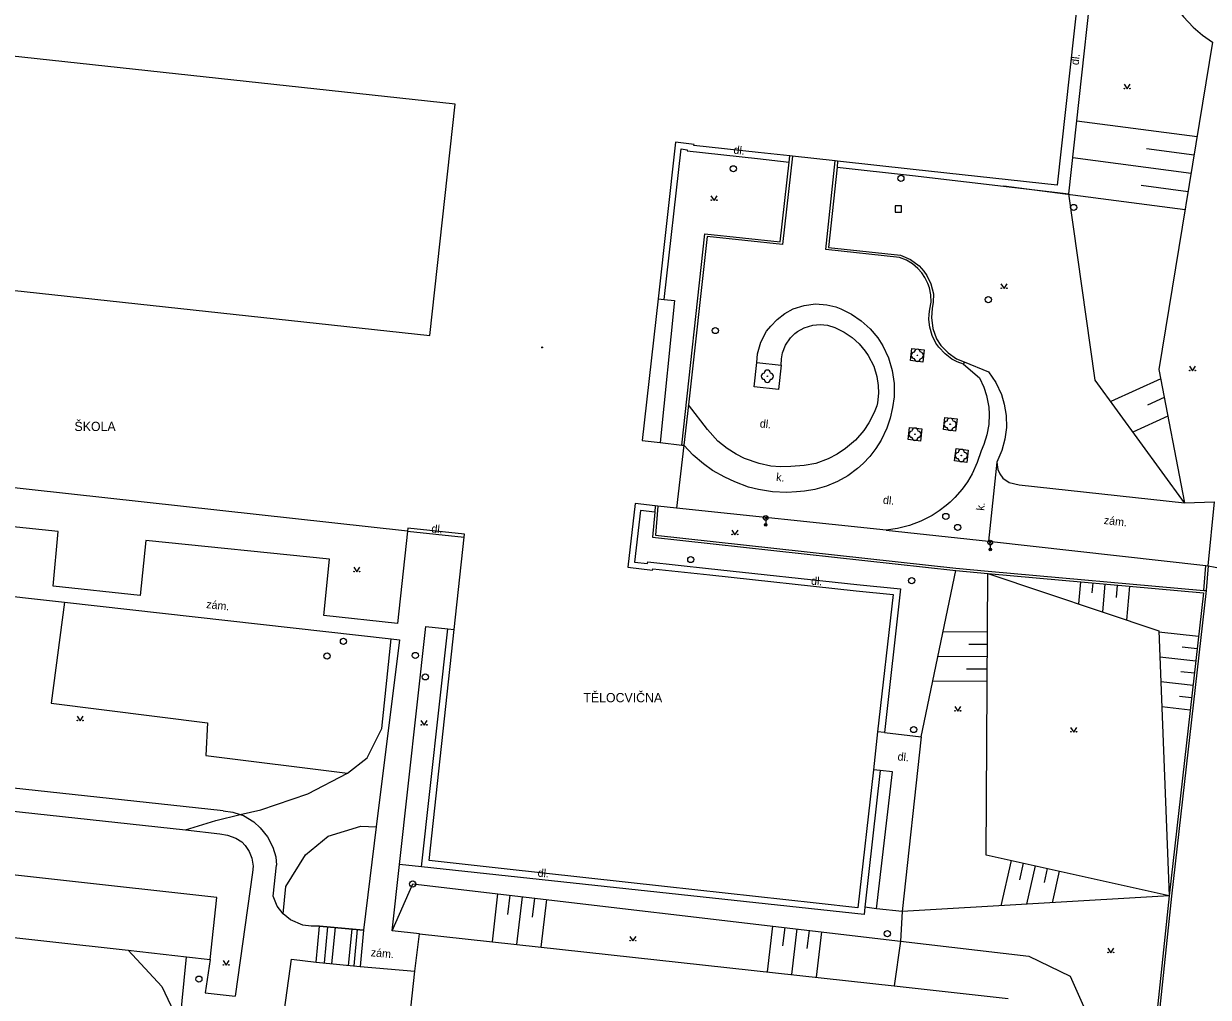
# Model space of a CAD drawing. Extents: x -602419 to -601554, y -1162937 to -1162362.
# Drawn here: x -602349.4 to -602253.1, y -1162646.7 to -1162567.6 of the extents above; entities that cross this region are included whole.
import ezdxf

# ---------------------------------------------------------------- set-up
doc = ezdxf.new("R2010")
doc.units = 0
doc.layers.add('Podklad', color=7, linetype='Continuous')

msp = doc.modelspace()

# ---------------------------------------------------------------- linework, layer by layer
at = {"layer": 'Podklad'}
for p, q in [((-602289.2325, -1162607.9), (-602288.9675, -1162607.635)), ((-602289.2325, -1162607.635), (-602288.9675, -1162607.9)), ((-602289.1, -1162607.955), (-602289.1, -1162608.33)), ((-602270.9925, -1162609.9), (-602270.7275, -1162609.635)), ((-602270.9925, -1162609.635), (-602270.7275, -1162609.9)), ((-602270.86, -1162609.955), (-602270.86, -1162610.33))]:
    msp.add_line(p, q, dxfattribs=at)
for points in [[(-602262.7199, -1162556.14), (-602265.43, -1162580.74)], [(-602264.4699, -1162581.45), (-602261.75, -1162556.46)], [(-602255.9, -1162566.18), (-602255.17, -1162567.08), (-602254.37, -1162567.9), (-602253.62, -1162568.55), (-602252.8, -1162569.12)], [(-602314.34, -1162574.17), (-602363.05, -1162568.87)], [(-602252.8, -1162569.12), (-602257.1599, -1162595.7199), (-602255.08, -1162606.53)], [(-602259.99, -1162572.545), (-602259.74, -1162572.92), (-602259.49, -1162572.545)], [(-602316.38, -1162592.96), (-602314.34, -1162574.17)], [(-602254.06, -1162576.82), (-602263.83, -1162575.55)], [(-602296.42, -1162577.26), (-602297.85, -1162589.96)], [(-602294.92, -1162577.43), (-602296.42, -1162577.26)], [(-602294.93, -1162577.51), (-602294.92, -1162577.43)], [(-602289.71, -1162578.08), (-602294.93, -1162577.51)], [(-602297.34, -1162590.02), (-602295.96, -1162577.8), (-602295.48, -1162577.86), (-602295.49, -1162577.95), (-602289.76, -1162578.58), (-602287.2, -1162578.86)], [(-602286.94, -1162578.38), (-602287.75, -1162585.57), (-602293.86, -1162584.92), (-602295.38, -1162598.57)], [(-602287.14, -1162578.36), (-602289.71, -1162578.08)], [(-602287.2, -1162578.86), (-602287.14, -1162578.36)], [(-602286.94, -1162578.38), (-602287.14, -1162578.36)], [(-602283.46, -1162578.76), (-602286.94, -1162578.38)], [(-602254.55, -1162579.79), (-602264.15, -1162578.53)], [(-602254.3, -1162578.3), (-602258.18, -1162577.8)], [(-602287.93, -1162585.35), (-602287.2, -1162578.86)], [(-602278.23, -1162586.62), (-602284.2199, -1162585.9699), (-602283.46, -1162578.76)], [(-602283.31, -1162579.28), (-602284, -1162585.8), (-602278.1599, -1162586.43)], [(-602283.26, -1162578.79), (-602283.46, -1162578.76)], [(-602283.26, -1162578.79), (-602283.31, -1162579.28)], [(-602283.31, -1162579.28), (-602277.18, -1162579.96), (-602264.4699, -1162581.45)], [(-602277.12, -1162579.46), (-602283.26, -1162578.79)], [(-602265.43, -1162580.74), (-602277.12, -1162579.46)], [(-602255.03, -1162582.75), (-602269.77, -1162580.83)], [(-602254.79, -1162581.27), (-602258.6, -1162580.77)], [(-602293.55, -1162581.605), (-602293.3, -1162581.98), (-602293.05, -1162581.605)], [(-602255.08, -1162606.53), (-602262.35, -1162596.57), (-602264.4699, -1162581.45)], [(-602295.9099, -1162601.85), (-602294.04, -1162584.7)], [(-602294.04, -1162584.7), (-602287.93, -1162585.35)], [(-602273.04, -1162595.28), (-602273.56, -1162595.1), (-602273.98, -1162594.87), (-602274.53, -1162594.45), (-602275.05, -1162593.89), (-602275.27, -1162593.57), (-602275.57, -1162592.94), (-602275.76, -1162592.27), (-602275.85, -1162591.6599), (-602275.82, -1162591.21), (-602275.76, -1162590.81), (-602275.67, -1162590.23), (-602275.69, -1162589.65), (-602275.8, -1162589.08), (-602275.93, -1162588.7199), (-602276.17, -1162588.23), (-602276.43, -1162587.85), (-602276.74, -1162587.51), (-602277.18, -1162587.14), (-602277.67, -1162586.83), (-602278.23, -1162586.62)], [(-602278.1599, -1162586.43), (-602277.35, -1162586.77), (-602276.63, -1162587.29), (-602276.25, -1162587.73), (-602276.01, -1162588.09), (-602275.68, -1162588.76), (-602275.48, -1162589.58), (-602275.49, -1162590.25), (-602275.57, -1162590.77), (-602275.63, -1162591.49), (-602275.52, -1162592.38), (-602275.2199, -1162593.21), (-602274.87, -1162593.77), (-602274.28, -1162594.37), (-602273.59, -1162594.85), (-602272.98, -1162595.09)], [(-602365.1, -1162587.6599), (-602316.38, -1162592.96)], [(-602269.99, -1162588.765), (-602269.74, -1162589.14), (-602269.49, -1162588.765)], [(-602297.85, -1162589.96), (-602299.15, -1162601.49)], [(-602297.85, -1162589.96), (-602297.34, -1162590.02)], [(-602297.34, -1162590.02), (-602296.5, -1162590.11)], [(-602296.5, -1162590.11), (-602297.67, -1162601.65)], [(-602289.82, -1162595.14), (-602289.76, -1162594.45), (-602289.49, -1162593.49), (-602289.03, -1162592.6), (-602288.69, -1162592.19), (-602288.18, -1162591.65), (-602287.55, -1162591.17), (-602286.86, -1162590.79), (-602285.98, -1162590.51), (-602285.06, -1162590.38), (-602284.14, -1162590.45), (-602283.4, -1162590.62), (-602283, -1162590.78), (-602282.14, -1162591.21), (-602281.34, -1162591.76), (-602280.63, -1162592.4099), (-602280, -1162593.15), (-602279.6, -1162593.79), (-602279.13, -1162594.76), (-602278.82, -1162595.79), (-602278.6599, -1162596.86), (-602278.6599, -1162597.94), (-602278.8, -1162598.8), (-602278.99, -1162599.6599), (-602279.27, -1162600.49), (-602279.73, -1162601.45), (-602280.15, -1162602.13), (-602280.64, -1162602.77), (-602281.19, -1162603.35), (-602281.65, -1162603.75), (-602282.43, -1162604.34), (-602283.27, -1162604.82), (-602284.17, -1162605.19), (-602285.11, -1162605.46), (-602285.96, -1162605.59), (-602286.59, -1162605.65), (-602287.39, -1162605.69), (-602288.55, -1162605.64), (-602289.69, -1162605.45), (-602290.49, -1162605.27), (-602291.62, -1162604.85), (-602292.43, -1162604.4699), (-602293.42, -1162603.9099), (-602294.1599, -1162603.38), (-602295.01, -1162602.6599), (-602295.75, -1162601.87)], [(-602287.84, -1162595.36), (-602287.83, -1162594.85), (-602287.73, -1162594.35), (-602287.5, -1162593.73), (-602287.08, -1162593.13), (-602286.73, -1162592.79), (-602286.52, -1162592.62), (-602285.99, -1162592.33), (-602285.27, -1162592.1), (-602284.68, -1162592.06), (-602284.08, -1162592.11), (-602283.5, -1162592.3), (-602282.7199, -1162592.67), (-602282.08, -1162593.11), (-602281.51, -1162593.63), (-602281.01, -1162594.2199), (-602280.77, -1162594.58), (-602280.33, -1162595.44), (-602280.07, -1162596.27), (-602279.96, -1162597.02), (-602279.94, -1162597.63), (-602280.02, -1162598.42), (-602280.08, -1162598.67), (-602280.29, -1162599.21), (-602280.7199, -1162600.05), (-602281.14, -1162600.67), (-602281.8, -1162601.45), (-602282.61, -1162602.13), (-602283.3, -1162602.59), (-602284.02, -1162602.9699), (-602285.02, -1162603.34), (-602285.9699, -1162603.51), (-602287.07, -1162603.6), (-602287.89, -1162603.61), (-602288.7, -1162603.56), (-602289.63, -1162603.36), (-602290.83, -1162602.94), (-602291.5, -1162602.6), (-602292.23, -1162602.14), (-602292.98, -1162601.52), (-602293.84, -1162600.58)], [(-602277.2199, -1162594), (-602276.23, -1162594.12), (-602276.35, -1162595.11), (-602277.34, -1162594.99), (-602277.2199, -1162594)], [(-602287.84, -1162595.36), (-602288.07, -1162597.35), (-602290.04, -1162597.12), (-602289.82, -1162595.14)], [(-602289.82, -1162595.14), (-602287.84, -1162595.36)], [(-602272.98, -1162595.09), (-602273.04, -1162595.28)], [(-602273.04, -1162595.28), (-602271.73, -1162596.38)], [(-602272.98, -1162595.09), (-602271.01, -1162595.89)], [(-602254.68, -1162595.445), (-602254.43, -1162595.82), (-602254.18, -1162595.445)], [(-602271.73, -1162596.38), (-602271.39, -1162597.14), (-602271.1599, -1162597.83), (-602270.9699, -1162598.76), (-602270.95, -1162599.34), (-602270.9699, -1162600.18), (-602271.13, -1162601.01), (-602271.37, -1162601.81), (-602271.61, -1162602.33), (-602271.93, -1162603.27), (-602272.34, -1162604.18), (-602272.71, -1162604.83), (-602273.15, -1162605.43), (-602273.73, -1162606.12), (-602274.11, -1162606.48), (-602274.44, -1162606.77), (-602275, -1162607.2), (-602275.59, -1162607.58), (-602276.49, -1162608.04), (-602277.43, -1162608.39), (-602278.4099, -1162608.64), (-602279.33, -1162608.75)], [(-602271.01, -1162595.89), (-602270.4, -1162596.77), (-602269.95, -1162597.74), (-602269.7199, -1162598.52), (-602269.57, -1162599.46), (-602269.55, -1162600.4099), (-602269.69, -1162601.36), (-602269.92, -1162602.28), (-602270.34, -1162603.23)], [(-602257.01, -1162596.48), (-602261.07, -1162598.32)], [(-602295.38, -1162598.57), (-602295.75, -1162601.87)], [(-602293.84, -1162600.58), (-602295.38, -1162598.57)], [(-602256.7199, -1162597.99), (-602258.1, -1162598.62)], [(-602274.55, -1162599.6), (-602273.56, -1162599.7199), (-602273.68, -1162600.71), (-602274.67, -1162600.59), (-602274.55, -1162599.6)], [(-602256.43, -1162599.5), (-602259.27, -1162600.79)], [(-602277.4099, -1162600.42), (-602276.42, -1162600.54), (-602276.54, -1162601.53), (-602277.53, -1162601.4099), (-602277.4099, -1162600.42)], [(-602299.15, -1162601.49), (-602297.67, -1162601.65)], [(-602297.67, -1162601.65), (-602295.9099, -1162601.85)], [(-602295.75, -1162601.87), (-602296.35, -1162606.98)], [(-602295.9099, -1162601.85), (-602295.75, -1162601.87)], [(-602273.64, -1162602.14), (-602272.65, -1162602.26), (-602272.77, -1162603.26), (-602273.77, -1162603.13), (-602273.64, -1162602.14)], [(-602318.2, -1162608.84), (-602319.03, -1162616.33), (-602325, -1162615.68), (-602324.53, -1162611.13), (-602339.45, -1162609.59), (-602339.9099, -1162614.08), (-602346.99, -1162613.31), (-602346.58, -1162608.86), (-602361.42, -1162607.34), (-602361.92, -1162611.68), (-602367.9099, -1162611.02), (-602367.1599, -1162603.46)], [(-602318.2, -1162608.84), (-602367.1599, -1162603.46)], [(-602270.34, -1162603.23), (-602271, -1162609.6599)], [(-602270.34, -1162603.23), (-602270.25, -1162603.84), (-602270.08, -1162604.2), (-602269.83, -1162604.55), (-602269.33, -1162604.89), (-602268.51, -1162605.07)], [(-602268.51, -1162605.07), (-602255.08, -1162606.53)], [(-602299.7199, -1162606.6), (-602300.31, -1162611.78)], [(-602298.12, -1162607.31), (-602299.27, -1162607.1599), (-602299.75, -1162611.35), (-602298.71, -1162611.46), (-602298.69, -1162611.34), (-602293.75, -1162611.87), (-602281.71, -1162613.18), (-602278.1599, -1162613.52), (-602279.46, -1162625.21)], [(-602298.08, -1162606.78), (-602299.7199, -1162606.6)], [(-602298.12, -1162607.31), (-602298.29, -1162609.34), (-602273.67, -1162612.05)], [(-602298.08, -1162606.78), (-602298.12, -1162607.31)], [(-602297.88, -1162606.81), (-602298.08, -1162606.78)], [(-602297.88, -1162606.81), (-602298.07, -1162609.1599), (-602273.65, -1162611.85), (-602271.03, -1162612.08), (-602253.52, -1162613.65)], [(-602296.35, -1162606.98), (-602297.88, -1162606.81)], [(-602279.33, -1162608.75), (-602296.35, -1162606.98)], [(-602255.08, -1162606.53), (-602252.64, -1162606.46)], [(-602253.1599, -1162611.65), (-602252.64, -1162606.46)], [(-602318.18, -1162608.59), (-602318.2, -1162608.84)], [(-602318.2, -1162608.84), (-602313.59, -1162609.34)], [(-602313.56, -1162609.1), (-602318.18, -1162608.59)], [(-602313.59, -1162609.34), (-602313.56, -1162609.1)], [(-602291.85, -1162608.755), (-602291.6, -1162609.13), (-602291.35, -1162608.755)], [(-602279.33, -1162608.75), (-602271, -1162609.6599)], [(-602314.4, -1162616.84), (-602313.59, -1162609.34)], [(-602271, -1162609.6599), (-602253.36, -1162611.63)], [(-602322.57, -1162611.775), (-602322.32, -1162612.15), (-602322.07, -1162611.775)], [(-602300.31, -1162611.78), (-602298.3, -1162612)], [(-602298.3, -1162612), (-602298.28, -1162611.89)], [(-602298.28, -1162611.89), (-602293.64, -1162612.39)], [(-602276.4699, -1162625.54), (-602273.67, -1162612.05)], [(-602273.67, -1162612.05), (-602271.05, -1162612.28)], [(-602253.52, -1162613.65), (-602253.36, -1162611.63)], [(-602253.36, -1162611.63), (-602253.1599, -1162611.65)], [(-602253.1599, -1162611.65), (-602253.31, -1162613.67)], [(-602253.1599, -1162611.65), (-602252.02, -1162611.88), (-602250.77, -1162612.48), (-602249.88, -1162613.05), (-602249.07, -1162613.87), (-602248.38, -1162614.79), (-602247.8, -1162616.04), (-602247.58, -1162617.08), (-602247.4699, -1162618.25)], [(-602333.18, -1162631.55), (-602369.52, -1162627.62), (-602367.45, -1162612.23), (-602346.07, -1162614.62), (-602319.53, -1162617.6), (-602318.86, -1162617.67), (-602320.74, -1162632.85), (-602321.78, -1162641.24)], [(-602293.64, -1162612.39), (-602281.76, -1162613.68)], [(-602256.33, -1162638.4699), (-602271.18, -1162635.15), (-602271.05, -1162612.28)], [(-602271.05, -1162612.28), (-602257.1599, -1162616.95), (-602256.33, -1162638.4699)], [(-602271.05, -1162612.28), (-602253.53, -1162613.85)], [(-602263.53, -1162612.95), (-602263.69, -1162614.75)], [(-602262.54, -1162613.04), (-602262.61, -1162613.86)], [(-602261.54, -1162613.13), (-602261.74, -1162615.4099)], [(-602406.42, -1162613.44), (-602407.63, -1162625.26), (-602370.74, -1162629.36), (-602336.25, -1162633.11), (-602333.45, -1162633.42)], [(-602253.31, -1162613.67), (-602256.13, -1162638.49), (-602260, -1162675.31), (-602321, -1162675.4699), (-602331.82, -1162673.96)], [(-602281.76, -1162613.68), (-602278.76, -1162614)], [(-602278.76, -1162614), (-602280.01, -1162625.15)], [(-602260.55, -1162613.2199), (-602260.64, -1162614.23)], [(-602259.55, -1162613.31), (-602259.8, -1162616.06)], [(-602253.53, -1162613.85), (-602256.33, -1162638.4699)], [(-602253.52, -1162613.65), (-602253.31, -1162613.67)], [(-602346.07, -1162614.62), (-602347.16, -1162622.82), (-602334.46, -1162624.41), (-602334.59, -1162627.06), (-602323.08, -1162628.51), (-602321.47, -1162627.25), (-602320.28, -1162624.87), (-602319.53, -1162617.6)], [(-602319.46, -1162641.31), (-602318.86, -1162635.92), (-602316.71, -1162616.59)], [(-602279.8, -1162628.29), (-602281.04, -1162639.39), (-602281.1, -1162639.97), (-602317.06, -1162636.11), (-602314.92, -1162616.79)], [(-602316.71, -1162616.59), (-602314.92, -1162616.79)], [(-602316.45, -1162635.6), (-602314.4, -1162616.84)], [(-602314.92, -1162616.79), (-602314.4, -1162616.84)], [(-602271.08, -1162617.05), (-602274.7, -1162617.03)], [(-602253.93, -1162617.4099), (-602257.1599, -1162617.05)], [(-602271.08, -1162618.05), (-602272.61, -1162618.04)], [(-602254.05, -1162618.4), (-602255.28, -1162618.27)], [(-602271.09, -1162619.05), (-602275.12, -1162619.03)], [(-602254.1599, -1162619.4), (-602257.08, -1162619.07)], [(-602271.09, -1162620.05), (-602272.79, -1162620.04)], [(-602254.27, -1162620.39), (-602255.38, -1162620.27)], [(-602271.1, -1162621.05), (-602275.53, -1162621.02)], [(-602254.39, -1162621.39), (-602257, -1162621.09)], [(-602254.5, -1162622.38), (-602255.48, -1162622.27)], [(-602273.75, -1162623.085), (-602273.5, -1162623.46), (-602273.25, -1162623.085)], [(-602254.61, -1162623.37), (-602256.92, -1162623.11)], [(-602345.05, -1162623.875), (-602344.8, -1162624.25), (-602344.55, -1162623.875)], [(-602317.11, -1162624.225), (-602316.86, -1162624.6), (-602316.61, -1162624.225)], [(-602280.01, -1162625.15), (-602280.35, -1162628.2199)], [(-602279.46, -1162625.21), (-602280.01, -1162625.15)], [(-602279.46, -1162625.21), (-602276.4699, -1162625.54)], [(-602276.4699, -1162625.54), (-602278.02, -1162639.74)], [(-602264.33, -1162624.7849), (-602264.08, -1162625.1599), (-602263.83, -1162624.7849)], [(-602336.25, -1162633.11), (-602333.77, -1162632.35), (-602331.8, -1162631.86), (-602330.13, -1162631.49), (-602326.3, -1162630.17), (-602323.08, -1162628.51)], [(-602280.35, -1162628.2199), (-602281.61, -1162639.44)], [(-602279.8, -1162628.29), (-602280.35, -1162628.2199)], [(-602278.02, -1162639.74), (-602280.1, -1162639.51), (-602278.8, -1162628.4), (-602279.8, -1162628.29)], [(-602334.24, -1162643.63), (-602333.7, -1162638.61), (-602399.43, -1162631.32), (-602413.2, -1162629.79), (-602413.76, -1162634.8), (-602399.17, -1162636.42), (-602340.91, -1162642.88), (-602336.16, -1162643.41)], [(-602333.18, -1162631.55), (-602332.4, -1162631.66), (-602331.8, -1162631.86), (-602331.53, -1162631.95), (-602330.68, -1162632.46), (-602330.17, -1162632.93), (-602329.57, -1162633.66), (-602329.14, -1162634.5), (-602328.91, -1162635.3), (-602328.85, -1162635.98)], [(-602328.31, -1162639.93), (-602328.08, -1162637.71), (-602326.5, -1162635.13), (-602324.64, -1162633.61), (-602322, -1162632.81), (-602320.74, -1162632.85)], [(-602333.45, -1162633.42), (-602332.82, -1162633.53), (-602332.15, -1162633.77), (-602331.67, -1162634.09), (-602331.39, -1162634.38), (-602331.06, -1162634.87), (-602330.84, -1162635.4099), (-602330.74, -1162636.05), (-602330.79, -1162636.58)], [(-602329.12, -1162638.49), (-602328.85, -1162635.98)], [(-602317.06, -1162636.11), (-602318.86, -1162635.92)], [(-602310.36, -1162636.27), (-602316.45, -1162635.6)], [(-602297.32, -1162637.71), (-602310.36, -1162636.27)], [(-602269.17, -1162635.6), (-602269.99, -1162639.27)], [(-602268.19, -1162635.82), (-602268.49, -1162637.17)], [(-602267.21, -1162636.04), (-602267.9099, -1162639.15)], [(-602266.24, -1162636.25), (-602266.49, -1162637.39)], [(-602340.91, -1162642.88), (-602338.17, -1162645.84), (-602336.71, -1162648.92), (-602335.81, -1162650.8), (-602334.91, -1162655.6), (-602335.55, -1162661.39), (-602338.33, -1162666.79), (-602341.98, -1162671), (-602347.06, -1162674.09), (-602351.26, -1162675.28), (-602355.87, -1162675.28), (-602392.78, -1162671.16), (-602397.78, -1162669.49), (-602400.24, -1162668.06), (-602403.1, -1162665.2), (-602405.72, -1162661.55), (-602407.46, -1162657.03), (-602408.02, -1162652.26), (-602407.38, -1162647.82), (-602405.56, -1162643.45), (-602402.94, -1162639.88), (-602400.24, -1162637.5), (-602399.17, -1162636.42)], [(-602330.79, -1162636.58), (-602332.21, -1162646.62)], [(-602265.26, -1162636.4699), (-602265.83, -1162639.03)], [(-602319.46, -1162641.31), (-602317.78, -1162637.5)], [(-602317.78, -1162637.5), (-602278.15, -1162642.14), (-602267.72, -1162643.36), (-602264.36, -1162645), (-602263.28, -1162647.42), (-602266.06, -1162675.13)], [(-602285.01, -1162639.06), (-602297.32, -1162637.71)], [(-602325.35, -1162640.93), (-602326.04, -1162640.93), (-602326.7199, -1162640.84), (-602327.7, -1162640.42), (-602328.31, -1162639.93), (-602328.78, -1162639.3), (-602329.12, -1162638.49)], [(-602310.88, -1162638.31), (-602311.33, -1162642.19)], [(-602309.89, -1162638.42), (-602310.07, -1162639.9699)], [(-602308.89, -1162638.54), (-602309.34, -1162642.4099)], [(-602307.9, -1162638.6599), (-602308.08, -1162640.2)], [(-602306.9099, -1162638.77), (-602307.36, -1162642.62)], [(-602281.61, -1162639.44), (-602285.01, -1162639.06)], [(-602256.33, -1162638.4699), (-602278.02, -1162639.74)], [(-602256.33, -1162638.4699), (-602260.18, -1162675.11), (-602266.06, -1162675.13)], [(-602280.1, -1162639.51), (-602281.04, -1162639.39)], [(-602278.02, -1162639.74), (-602278.15, -1162642.14), (-602278.67, -1162645.77)], [(-602325.63, -1162643.85), (-602325.35, -1162640.93)], [(-602325.35, -1162640.93), (-602321.78, -1162641.24)], [(-602321.78, -1162641.24), (-602325.35, -1162640.93)], [(-602324.7, -1162640.99), (-602324.98, -1162643.9099)], [(-602324.34, -1162643.98), (-602324.06, -1162641.04)], [(-602288.55, -1162640.92), (-602288.99, -1162644.64)], [(-602287.56, -1162641.04), (-602287.73, -1162642.52)], [(-602322.74, -1162641.1599), (-602323.03, -1162644.11)], [(-602322.54, -1162644.15), (-602322.26, -1162641.2)], [(-602321.78, -1162641.24), (-602322.06, -1162644.2)], [(-602317.24, -1162641.54), (-602319.46, -1162641.31)], [(-602317.62, -1162644.58), (-602317.24, -1162641.54)], [(-602317.24, -1162641.54), (-602278.67, -1162645.77), (-602269.4, -1162646.79)], [(-602300.14, -1162641.755), (-602299.89, -1162642.13), (-602299.64, -1162641.755)], [(-602286.57, -1162641.15), (-602287, -1162644.86)], [(-602285.57, -1162641.27), (-602285.75, -1162642.75)], [(-602284.58, -1162641.39), (-602285.01, -1162645.08)], [(-602261.31, -1162642.705), (-602261.06, -1162643.08), (-602260.81, -1162642.705)], [(-602332.81, -1162651.12), (-602335.81, -1162650.8), (-602336.88, -1162650.68), (-602336.71, -1162648.92), (-602336.16, -1162643.41)], [(-602336.1599, -1162643.4099), (-602334.24, -1162643.63)], [(-602334.24, -1162643.63), (-602334.64, -1162646.35), (-602332.21, -1162646.62)], [(-602333.19, -1162643.725), (-602332.94, -1162644.1), (-602332.69, -1162643.725)], [(-602331.79, -1162673.76), (-602327.62, -1162643.61)], [(-602327.62, -1162643.61), (-602325.63, -1162643.85)], [(-602325.63, -1162643.85), (-602322.06, -1162644.2)], [(-602325.63, -1162643.85), (-602322.06, -1162644.2)], [(-602322.06, -1162644.2), (-602317.62, -1162644.58)], [(-602320.1, -1162667.64), (-602317.62, -1162644.58)]]:
    msp.add_lwpolyline(points, dxfattribs=at)
msp.add_lwpolyline([(-602278.58, -1162582.93), (-602278.08, -1162582.93), (-602278.08, -1162582.43), (-602278.58, -1162582.43)], close=True, dxfattribs=at)
for centre, radius in [((-602259.9651, -1162572.8949), 0.025), ((-602259.5154, -1162572.8949), 0.025), ((-602291.73, -1162579.4099), 0.25), ((-602278.12, -1162580.18), 0.25), ((-602293.5251, -1162581.9549), 0.025), ((-602293.0754, -1162581.9549), 0.025), ((-602264.08, -1162582.55), 0.25), ((-602269.9651, -1162589.1149), 0.025), ((-602269.5154, -1162589.1149), 0.025), ((-602271.02, -1162590.04), 0.25), ((-602293.2, -1162592.55), 0.25), ((-602307.27, -1162593.92), 0.045), ((-602307.27, -1162593.92), 0.0199), ((-602276.78, -1162594.56), 0.025), ((-602254.6551, -1162595.7949), 0.025), ((-602254.2054, -1162595.7949), 0.025), ((-602288.9699, -1162596.26), 0.025), ((-602274.12, -1162600.1599), 0.025), ((-602276.98, -1162600.9699), 0.025), ((-602273.21, -1162602.7), 0.025), ((-602274.4699, -1162607.65), 0.25), ((-602289.1, -1162607.7675), 0.1875), ((-602289.1, -1162608.33), 0.1), ((-602289.1, -1162608.33), 0.0723), ((-602289.1, -1162608.33), 0.0438), ((-602273.51, -1162608.54), 0.25), ((-602291.8251, -1162609.1049), 0.025), ((-602291.3754, -1162609.1049), 0.025), ((-602270.86, -1162609.7675), 0.1875), ((-602270.86, -1162610.33), 0.1), ((-602270.86, -1162610.33), 0.0723), ((-602270.86, -1162610.33), 0.0438), ((-602295.19, -1162611.15), 0.25), ((-602322.5451, -1162612.1249), 0.025), ((-602322.0954, -1162612.1249), 0.025), ((-602277.24, -1162612.86), 0.25), ((-602323.4099, -1162617.79), 0.25), ((-602324.74, -1162618.98), 0.25), ((-602317.57, -1162618.94), 0.25), ((-602316.76, -1162620.68), 0.25), ((-602273.7251, -1162623.4349), 0.025), ((-602273.2754, -1162623.4349), 0.025), ((-602345.0251, -1162624.2249), 0.025), ((-602344.5754, -1162624.2249), 0.025), ((-602317.0851, -1162624.5749), 0.025), ((-602316.6354, -1162624.5749), 0.025), ((-602277.08, -1162624.96), 0.25), ((-602264.3051, -1162625.1348), 0.025), ((-602263.8554, -1162625.1348), 0.025), ((-602317.78, -1162637.5), 0.25), ((-602279.2199, -1162641.54), 0.25), ((-602300.1151, -1162642.1049), 0.025), ((-602299.6654, -1162642.1049), 0.025), ((-602261.2851, -1162643.0549), 0.025), ((-602260.8354, -1162643.0549), 0.025), ((-602333.1651, -1162644.0749), 0.025), ((-602332.7154, -1162644.0749), 0.025), ((-602335.15, -1162645.23), 0.25)]:
    msp.add_circle(centre, radius, dxfattribs=at)
for centre, start, end in [((-602277.03, -1162594.56), 90, 270), ((-602276.78, -1162594.31), 0, 180), ((-602276.78, -1162594.81), 180, 0), ((-602276.53, -1162594.56), 270, 90), ((-602288.9699, -1162596.01), 0, 180), ((-602289.2199, -1162596.26), 90, 270), ((-602288.9699, -1162596.51), 180, 0), ((-602288.7199, -1162596.26), 270, 90), ((-602274.12, -1162599.9099), 0, 180), ((-602276.98, -1162600.7199), 0, 180), ((-602274.37, -1162600.1599), 90, 270), ((-602274.12, -1162600.4099), 180, 0), ((-602273.87, -1162600.1599), 270, 90), ((-602277.23, -1162600.9699), 90, 270), ((-602276.98, -1162601.2199), 180, 0), ((-602276.73, -1162600.9699), 270, 90), ((-602273.46, -1162602.7), 90, 270), ((-602273.21, -1162602.45), 0, 180), ((-602272.96, -1162602.7), 270, 90), ((-602273.21, -1162602.95), 180, 0)]:
    msp.add_arc(centre, 0.25, start, end, dxfattribs=at)

# ---------------------------------------------------------------- texts
for s, rotation, p in [('dl.', 83.07, (-602263.69, -1162571.01)), ('dl.', 353.73, (-602291.75, -1162578.18)), ('dl.', 353.81, (-602289.61, -1162600.4099)), ('k.', 353.81, (-602288.28, -1162604.75)), ('dl.', 353.81, (-602279.6, -1162606.61)), ('k.', 84.28, (-602271.36, -1162607.2)), ('dl.', 353.81, (-602316.29, -1162608.94)), (' zám.', 353.63, (-602261.9, -1162608.23)), ('dl.', 355.11, (-602285.44, -1162613.18)), (' zám.', 353.81, (-602334.82, -1162615.06)), ('dl.', 355.11, (-602278.4099, -1162627.46)), ('dl.', 355.11, (-602307.65, -1162636.9)), (' zám.', 355.11, (-602321.45, -1162643.35))]:
    msp.add_text(s, height=0.65, rotation=rotation, dxfattribs=at).set_placement(p)
for s, p in [('ŠKOLA', (-602345.26, -1162600.71)), ('TĚLOCVIČNA', (-602303.92, -1162622.74))]:
    msp.add_text(s, height=0.75, dxfattribs=at).set_placement(p)

doc.saveas('drawing.dxf')
